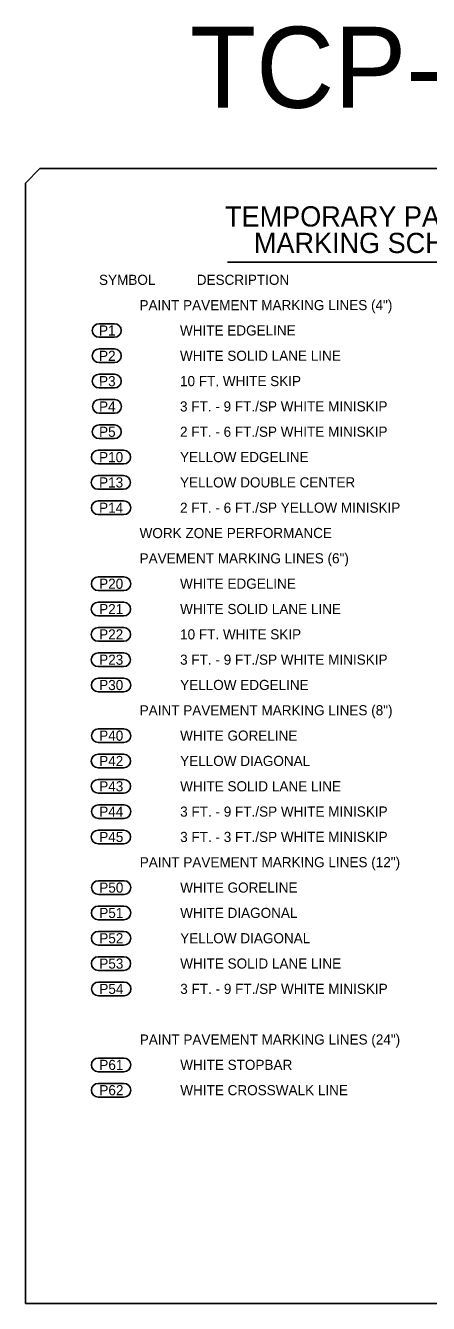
# Model space of a CAD drawing. Extents: x 2486454 to 2490507, y 369321 to 372999.
# Drawn here: x 2487348 to 2487627, y 369321 to 370204 of the extents above; entities that cross this region are included whole.
import ezdxf

# ---------------------------------------------------------------- set-up
doc = ezdxf.new("R2010")
doc.units = 0
for name, color, linetype in [('Default', 7, 'Continuous'), ('TC LABEL PM', 7, 'Continuous'), ('TC SHEET BORDER LINE THIN', 7, 'Continuous'), ('TC SHEET LAYOUT SHAPE', 7, 'Continuous'), ('TC SHEET TEXT', 7, 'Continuous')]:
    doc.layers.add(name, color=color, linetype=linetype)

msp = doc.modelspace()

# ---------------------------------------------------------------- linework, layer by layer
at = {"layer": 'TC LABEL PM'}
for p, q in [((2487410, 369997.89), (2487399.33, 369997.89)), ((2487399.33, 369988.46), (2487410, 369988.46)), ((2487410, 369980.39), (2487399.33, 369980.39)), ((2487409.98, 369962.89), (2487399.31, 369962.89)), ((2487399.33, 369970.96), (2487410, 369970.96)), ((2487399.31, 369953.46), (2487409.98, 369953.46)), ((2487410.16, 369945.39), (2487399.5, 369945.39)), ((2487399.5, 369935.96), (2487410.16, 369935.96)), ((2487410.01, 369927.89), (2487399.34, 369927.89)), ((2487399.34, 369918.46), (2487410.01, 369918.46)), ((2487416.48, 369910.39), (2487398.73, 369910.39)), ((2487398.73, 369900.96), (2487416.48, 369900.96)), ((2487416.35, 369892.89), (2487398.59, 369892.89)), ((2487398.59, 369883.46), (2487416.35, 369883.46)), ((2487416.53, 369875.39), (2487398.77, 369875.39)), ((2487398.77, 369865.96), (2487416.53, 369865.96)), ((2487416.52, 369822.89), (2487398.76, 369822.89)), ((2487398.76, 369813.46), (2487416.52, 369813.46)), ((2487416.42, 369805.39), (2487398.66, 369805.39)), ((2487398.66, 369795.96), (2487416.42, 369795.96)), ((2487416.42, 369787.89), (2487398.66, 369787.89)), ((2487398.66, 369778.46), (2487416.42, 369778.46)), ((2487416.4, 369770.39), (2487398.64, 369770.39)), ((2487398.64, 369760.96), (2487416.4, 369760.96)), ((2487416.55, 369752.89), (2487398.79, 369752.89)), ((2487398.79, 369743.46), (2487416.55, 369743.46)), ((2487416.57, 369717.89), (2487398.81, 369717.89)), ((2487398.81, 369708.46), (2487416.57, 369708.46)), ((2487416.46, 369700.39), (2487398.7, 369700.39)), ((2487398.7, 369690.96), (2487416.46, 369690.96)), ((2487416.44, 369682.89), (2487398.68, 369682.89)), ((2487398.68, 369673.46), (2487416.44, 369673.46)), ((2487416.62, 369665.39), (2487398.86, 369665.39)), ((2487398.86, 369655.96), (2487416.62, 369655.96)), ((2487416.46, 369647.89), (2487398.71, 369647.89)), ((2487398.71, 369638.46), (2487416.46, 369638.46)), ((2487416.61, 369612.89), (2487398.85, 369612.89)), ((2487398.85, 369603.46), (2487416.61, 369603.46)), ((2487416.51, 369595.39), (2487398.75, 369595.39)), ((2487398.75, 369585.96), (2487416.51, 369585.96)), ((2487416.51, 369577.89), (2487398.75, 369577.89)), ((2487398.75, 369568.46), (2487416.51, 369568.46)), ((2487416.49, 369560.39), (2487398.73, 369560.39)), ((2487398.73, 369550.96), (2487416.49, 369550.96)), ((2487416.67, 369542.89), (2487398.92, 369542.89)), ((2487398.92, 369533.46), (2487416.67, 369533.46)), ((2487416.55, 369490.39), (2487398.8, 369490.39)), ((2487398.8, 369480.96), (2487416.55, 369480.96)), ((2487416.56, 369472.89), (2487398.8, 369472.89)), ((2487398.8, 369463.46), (2487416.56, 369463.46))]:
    msp.add_line(p, q, dxfattribs=at)
for centre, start, end in [((2487399.33, 369993.17), 90, 270), ((2487410, 369993.17), 270, 90), ((2487399.33, 369975.67), 90, 270), ((2487410, 369975.67), 270, 90), ((2487399.31, 369958.17), 90, 270), ((2487409.98, 369958.17), 270, 90), ((2487399.5, 369940.67), 90, 270), ((2487410.16, 369940.67), 270, 90), ((2487399.34, 369923.17), 90, 270), ((2487410.01, 369923.17), 270, 90), ((2487398.73, 369905.67), 90, 270), ((2487416.48, 369905.67), 270, 90), ((2487398.59, 369888.17), 90, 270), ((2487416.35, 369888.17), 270, 90), ((2487398.77, 369870.67), 90, 270), ((2487416.53, 369870.67), 270, 90), ((2487398.76, 369818.17), 90, 270), ((2487416.52, 369818.17), 270, 90), ((2487398.66, 369800.67), 90, 270), ((2487416.42, 369800.67), 270, 90), ((2487398.66, 369783.17), 90, 270), ((2487416.42, 369783.17), 270, 90), ((2487398.64, 369765.67), 90, 270), ((2487416.4, 369765.67), 270, 90), ((2487398.79, 369748.17), 90, 270), ((2487416.55, 369748.17), 270, 90), ((2487398.81, 369713.17), 90, 270), ((2487416.57, 369713.17), 270, 90), ((2487398.7, 369695.67), 90, 270), ((2487416.46, 369695.67), 270, 90), ((2487398.68, 369678.17), 90, 270), ((2487416.44, 369678.17), 270, 90), ((2487398.86, 369660.67), 90, 270), ((2487416.62, 369660.67), 270, 90), ((2487398.71, 369643.17), 90, 270), ((2487416.46, 369643.17), 270, 90), ((2487398.85, 369608.17), 90, 270), ((2487416.61, 369608.17), 270, 90), ((2487398.75, 369590.67), 90, 270), ((2487416.51, 369590.67), 270, 90), ((2487398.75, 369573.17), 90, 270), ((2487416.51, 369573.17), 270, 90), ((2487398.73, 369555.67), 90, 270), ((2487416.49, 369555.67), 270, 90), ((2487398.92, 369538.17), 90, 270), ((2487416.67, 369538.17), 270, 90), ((2487398.8, 369485.67), 90, 270), ((2487416.55, 369485.67), 270, 90), ((2487398.8, 369468.17), 90, 270), ((2487416.56, 369468.17), 270, 90)]:
    msp.add_arc(centre, 4.72, start, end, dxfattribs=at)
at = {"layer": 'TC SHEET BORDER LINE THIN'}
msp.add_line((2487488.27, 370040.3), (2487808.8, 370040.3), dxfattribs=at)
at = {"layer": 'TC SHEET LAYOUT SHAPE'}
msp.add_lwpolyline([(2487348.46, 370095.07), (2487358.46, 370105.07), (2487994.1, 370105.07), (2487994.1, 369320.81), (2487348.46, 369320.81)], close=True, dxfattribs=at)

# ---------------------------------------------------------------- texts
at = {"layer": 'Default'}
for s, p in [('SYMBOL           DESCRIPTION', (2487399.31, 370024.67)), ('PAINT PAVEMENT MARKING LINES (4")', (2487427.32, 370007.18)), ('P1', (2487399.32, 369989.67)), ('WHITE EDGELINE', (2487455.32, 369989.69)), ('P2', (2487399.33, 369972.17)), ('WHITE SOLID LANE LINE', (2487455.33, 369972.19)), ('P3', (2487399.34, 369954.67)), ('10 FT. WHITE SKIP', (2487455.34, 369954.69)), ('3 FT. - 9 FT./SP WHITE MINISKIP', (2487455.35, 369937.19)), ('P4', (2487399.35, 369937.17)), ('2 FT. - 6 FT./SP WHITE MINISKIP', (2487455.35, 369919.69)), ('P5', (2487399.35, 369919.67)), ('P10', (2487399.36, 369902.17)), ('YELLOW EDGELINE', (2487455.36, 369902.19)), ('P13', (2487399.37, 369884.67)), ('YELLOW DOUBLE CENTER', (2487455.37, 369884.69)), ('P14', (2487399.38, 369867.17)), ('2 FT. - 6 FT./SP YELLOW MINISKIP', (2487455.38, 369867.19)), ('WORK ZONE PERFORMANCE', (2487427.38, 369849.68)), ('PAVEMENT MARKING LINES (6")', (2487427.39, 369832.18)), ('P20', (2487399.4, 369814.67)), ('WHITE EDGELINE', (2487455.4, 369814.69)), ('P21', (2487399.41, 369797.17)), ('WHITE SOLID LANE LINE', (2487455.41, 369797.19)), ('P22', (2487399.41, 369779.67)), ('10 FT. WHITE SKIP', (2487455.41, 369779.69)), ('P23', (2487399.42, 369762.17)), ('3 FT. - 9 FT./SP WHITE MINISKIP', (2487455.42, 369762.19)), ('P30', (2487399.43, 369744.67)), ('YELLOW EDGELINE', (2487455.43, 369744.69)), ('PAINT PAVEMENT MARKING LINES (8")', (2487427.44, 369727.18)), ('P40', (2487399.44, 369709.67)), ('WHITE GORELINE', (2487455.44, 369709.69)), ('P42', (2487399.45, 369692.17)), ('YELLOW DIAGONAL', (2487455.45, 369692.19)), ('P43', (2487399.46, 369674.67)), ('WHITE SOLID LANE LINE', (2487455.46, 369674.69)), ('P44', (2487399.47, 369657.17)), ('3 FT. - 9 FT./SP WHITE MINISKIP', (2487455.47, 369657.19)), ('P45', (2487399.47, 369639.67)), ('3 FT. - 3 FT./SP WHITE MINISKIP', (2487455.47, 369639.69)), ('PAINT PAVEMENT MARKING LINES (12")', (2487427.48, 369622.18)), ('P50', (2487399.49, 369604.67)), ('WHITE GORELINE', (2487455.49, 369604.69)), ('P51', (2487399.5, 369587.17)), ('WHITE DIAGONAL', (2487455.5, 369587.19)), ('P52', (2487399.5, 369569.67)), ('YELLOW DIAGONAL', (2487455.5, 369569.69)), ('P53', (2487399.51, 369552.17)), ('WHITE SOLID LANE LINE', (2487455.51, 369552.19)), ('P54', (2487399.52, 369534.67)), ('3 FT. - 9 FT./SP WHITE MINISKIP', (2487455.52, 369534.69)), ('PAINT PAVEMENT MARKING LINES (24")', (2487427.53, 369499.68)), ('P61', (2487399.54, 369482.17)), ('WHITE STOPBAR', (2487455.54, 369482.19)), ('P62', (2487399.55, 369464.67)), ('WHITE CROSSWALK LINE', (2487455.55, 369464.69))]:
    msp.add_text(s, height=7, rotation=0.02426, dxfattribs=at).set_placement(p)
at = {"layer": 'TC SHEET LAYOUT SHAPE'}
msp.add_text('TCP-01C', height=55.996, rotation=0.00008, dxfattribs=at).set_placement((2487462.21, 370147.07))
at = {"layer": 'TC SHEET TEXT'}
for s, p in [('TEMPORARY PAVEMENT', (2487486.52, 370065.03)), ('MARKING SCHEDULE', (2487506.46, 370046.67))]:
    msp.add_text(s, height=13.9991, rotation=0.00008, dxfattribs=at).set_placement(p)

doc.saveas('drawing.dxf')
